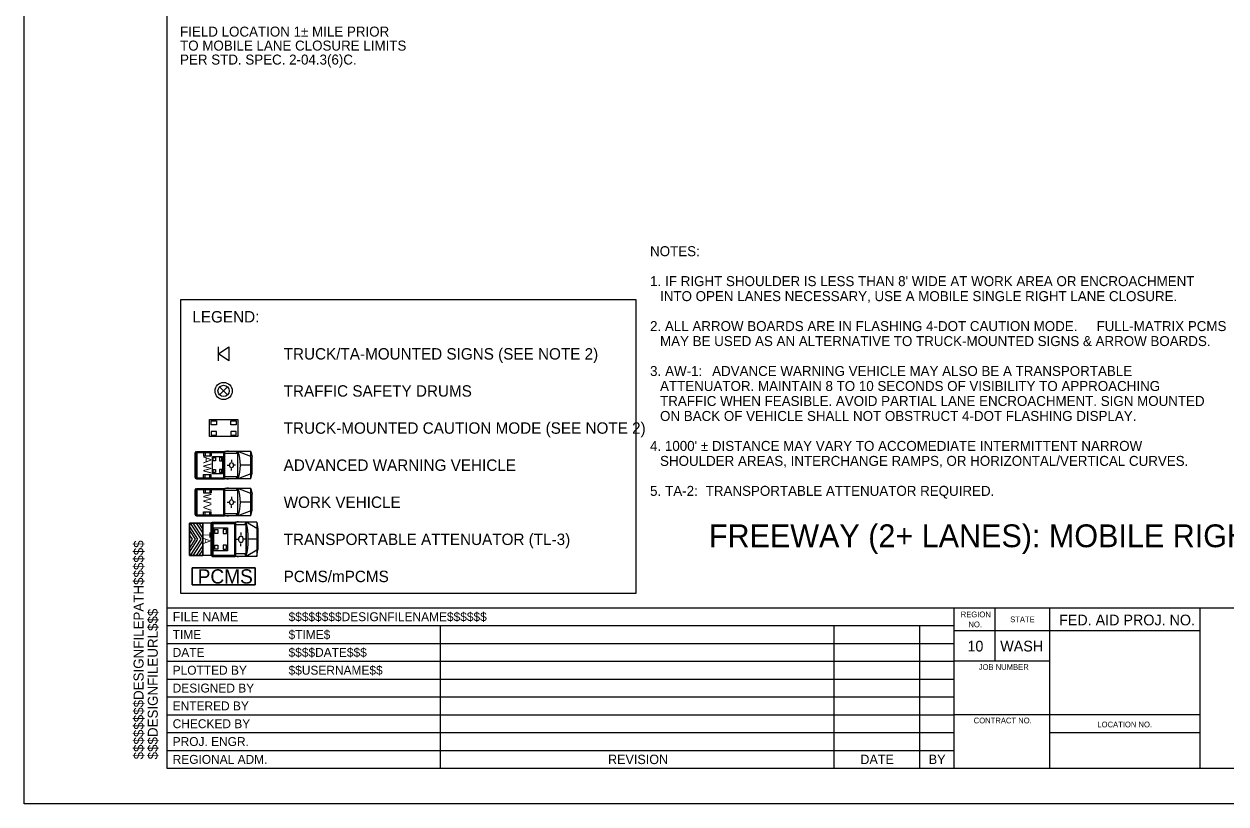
# Model space of a CAD drawing. Extents: x 0 to 17, y 0 to 11.
# Drawn here: x 0 to 8.43, y 0 to 5.47 of the extents above; entities that cross this region are included whole.
import ezdxf

# ---------------------------------------------------------------- set-up
doc = ezdxf.new("R2010")
doc.units = 0
for name, color, linetype in [('SH_GI_PlotLimits', 7, 'Continuous'), ('SH_GI_SheetBorder1', 7, 'Continuous'), ('SH_GI_SheetBorder2', 7, 'Continuous'), ('SH_GI_SheetBorder3', 7, 'Continuous'), ('SH_GI_SheetTextInCells', 7, 'Continuous'), ('SH_GI_TitleBlockText', 7, 'Continuous'), ('TR_WZ_PCMS', 7, 'Continuous'), ('TR_WZ_PortableChangeMessageSign', 7, 'Continuous'), ('TR_WZ_PortableSignMountBlk-Org', 7, 'Continuous'), ('TR_WZ_ProtectiveVehicle', 7, 'Continuous'), ('TR_WZ_TrafficSafetyDrum', 7, 'Continuous'), ('TR_WZ_TransportableAttenuator', 7, 'Continuous'), ('TR_WZ_WorkZoneTextCurrent', 7, 'Continuous')]:
    doc.layers.add(name, color=color, linetype=linetype)

msp = doc.modelspace()

# ---------------------------------------------------------------- linework, layer by layer
at = {"layer": 'SH_GI_PlotLimits'}
msp.add_lwpolyline([(0, 11), (17, 11), (17, 0), (0, 0)], close=True, dxfattribs=at)
at = {"layer": 'SH_GI_SheetBorder1'}
for p, q in [((8.245, 1.2125), (6.52, 1.2125)), ((1, 1.125), (2.92, 1.125)), ((2.92, 1.125), (6.52, 1.125)), ((1, 1), (2.92, 1)), ((2.92, 1), (6.52, 1)), ((1, 0.875), (2.92, 0.875)), ((2.92, 0.875), (6.52, 0.875)), ((1, 0.75), (2.92, 0.75)), ((2.92, 0.75), (6.52, 0.75)), ((1, 0.625), (2.92, 0.625)), ((2.92, 0.625), (6.52, 0.625)), ((1, 0.5), (2.92, 0.5)), ((2.92, 0.5), (6.52, 0.5)), ((7.1913, 0.5), (8.245, 0.5)), ((1, 0.375), (2.92, 0.375))]:
    msp.add_line(p, q, dxfattribs=at)
at = {"layer": 'SH_GI_SheetBorder2'}
for p, q in [((6.8073, 1), (6.8073, 1.375)), ((7.1913, 1), (6.52, 1)), ((8.245, 0.625), (6.52, 0.625)), ((2.92, 0.375), (6.52, 0.375))]:
    msp.add_line(p, q, dxfattribs=at)
at = {"layer": 'SH_GI_SheetBorder3'}
for p, q in [((1, 10.75), (1, 0.25)), ((1, 1.375), (16.75, 1.375)), ((6.52, 0.25), (6.52, 1.375)), ((7.1913, 0.25), (7.1913, 1.375)), ((8.245, 0.25), (8.245, 1.375)), ((1, 1.25), (6.52, 1.25)), ((2.92, 0.25), (2.92, 1.25)), ((5.68, 0.25), (5.68, 1.25)), ((6.28, 0.25), (6.28, 1.25)), ((1, 0.25), (16.75, 0.25))]:
    msp.add_line(p, q, dxfattribs=at)
at = {"layer": 'TR_WZ_PCMS'}
for points in [[(1.6191, 1.655), (1.6191, 1.535), (1.1791, 1.535), (1.1791, 1.655), (1.6191, 1.655)], [(1.1791, 1.655), (1.1791, 1.535), (1.6191, 1.535), (1.6191, 1.655), (1.1791, 1.655)]]:
    msp.add_lwpolyline(points, dxfattribs=at)
at = {"layer": 'TR_WZ_PortableSignMountBlk-Org'}
msp.add_line((1.3631, 3.105), (1.3631, 3.205), dxfattribs=at)
msp.add_lwpolyline([(1.3631, 3.155), (1.435, 3.205), (1.435, 3.105)], close=True, dxfattribs=at)
at = {"layer": 'TR_WZ_ProtectiveVehicle'}
for p, q in [((1.1993, 2.288), (1.1993, 2.462)), ((1.2035, 2.4678), (1.2078, 2.4678)), ((1.2078, 2.2822), (1.2078, 2.4678)), ((1.2085, 2.471), (1.406, 2.471)), ((1.2085, 2.279), (1.2085, 2.471)), ((1.2141, 2.2867), (1.2141, 2.4633)), ((1.2141, 2.4633), (1.4004, 2.4633)), ((1.2586, 2.4633), (1.2586, 2.4413)), ((1.2692, 2.4633), (1.2692, 2.4413)), ((1.3018, 2.4633), (1.3018, 2.4413)), ((1.3114, 2.4633), (1.3114, 2.4413)), ((1.4004, 2.2867), (1.4004, 2.4633)), ((1.406, 2.279), (1.406, 2.471)), ((1.4086, 2.279), (1.4086, 2.471)), ((1.59, 2.471), (1.4086, 2.471)), ((1.4976, 2.4561), (1.4086, 2.4561)), ((1.4334, 2.4737), (1.4225, 2.4737)), ((1.4881, 2.4561), (1.4976, 2.471)), ((1.4976, 2.279), (1.4976, 2.471)), ((1.4993, 2.279), (1.4993, 2.471)), ((1.59, 2.4358), (1.4993, 2.471)), ((1.59, 2.279), (1.59, 2.471)), ((1.59, 2.471), (1.5989, 2.4322)), ((1.1993, 2.3885), (1.2078, 2.3849)), ((1.1993, 2.3615), (1.2078, 2.3651)), ((1.2016, 2.375), (1.2055, 2.375)), ((1.2035, 2.3723), (1.2035, 2.3777)), ((1.2586, 2.4413), (1.3114, 2.4413)), ((1.4245, 2.3757), (1.4388, 2.3754)), ((1.4406, 2.3753), (1.4406, 2.3753)), ((1.4535, 2.4119), (1.4537, 2.3975)), ((1.4831, 2.3749), (1.471, 2.3749)), ((1.59, 2.375), (1.5171, 2.375)), ((1.5989, 2.3178), (1.5989, 2.4322)), ((1.2035, 2.2822), (1.2078, 2.2822)), ((1.2085, 2.279), (1.406, 2.279)), ((1.2141, 2.2867), (1.4004, 2.2867)), ((1.2586, 2.3087), (1.3114, 2.3087)), ((1.2586, 2.2867), (1.2586, 2.3087)), ((1.2692, 2.2867), (1.2692, 2.3087)), ((1.3018, 2.2867), (1.3018, 2.3087)), ((1.3114, 2.2867), (1.3114, 2.3087)), ((1.4976, 2.2939), (1.4086, 2.2939)), ((1.59, 2.279), (1.4086, 2.279)), ((1.4334, 2.2763), (1.4225, 2.2763)), ((1.4541, 2.3369), (1.4541, 2.3525)), ((1.4976, 2.279), (1.4861, 2.2939)), ((1.59, 2.3142), (1.4993, 2.279)), ((1.59, 2.279), (1.5989, 2.3178)), ((1.1993, 2.028), (1.1993, 2.202)), ((1.2035, 2.2078), (1.2078, 2.2078)), ((1.2078, 2.0222), (1.2078, 2.2078)), ((1.2085, 2.211), (1.406, 2.211)), ((1.2085, 2.019), (1.2085, 2.211)), ((1.2141, 2.0267), (1.2141, 2.2033)), ((1.2141, 2.2033), (1.4004, 2.2033)), ((1.2586, 2.2033), (1.2586, 2.1813)), ((1.2692, 2.2033), (1.2692, 2.1813)), ((1.3018, 2.2033), (1.3018, 2.1813)), ((1.3114, 2.2033), (1.3114, 2.1813)), ((1.4004, 2.0267), (1.4004, 2.2033)), ((1.406, 2.019), (1.406, 2.211)), ((1.4086, 2.019), (1.4086, 2.211)), ((1.59, 2.211), (1.4086, 2.211)), ((1.4976, 2.1961), (1.4086, 2.1961)), ((1.4334, 2.2137), (1.4225, 2.2137)), ((1.4881, 2.1961), (1.4976, 2.211)), ((1.4976, 2.019), (1.4976, 2.211)), ((1.4993, 2.019), (1.4993, 2.211)), ((1.59, 2.1758), (1.4993, 2.211)), ((1.59, 2.019), (1.59, 2.211)), ((1.59, 2.211), (1.5989, 2.1722)), ((1.1993, 2.1285), (1.2078, 2.1249)), ((1.2016, 2.115), (1.2055, 2.115)), ((1.2035, 2.1123), (1.2035, 2.1177)), ((1.2586, 2.1813), (1.3114, 2.1813)), ((1.4245, 2.1157), (1.4388, 2.1154)), ((1.4406, 2.1153), (1.4406, 2.1153)), ((1.4535, 2.1519), (1.4537, 2.1375)), ((1.4831, 2.1149), (1.471, 2.1149)), ((1.59, 2.115), (1.5171, 2.115)), ((1.5989, 2.0578), (1.5989, 2.1722)), ((1.1993, 2.1015), (1.2078, 2.1051)), ((1.2141, 2.0267), (1.4004, 2.0267)), ((1.2586, 2.0487), (1.3114, 2.0487)), ((1.2586, 2.0267), (1.2586, 2.0487)), ((1.2692, 2.0267), (1.2692, 2.0487)), ((1.3018, 2.0267), (1.3018, 2.0487)), ((1.3114, 2.0267), (1.3114, 2.0487)), ((1.4976, 2.0339), (1.4086, 2.0339)), ((1.4541, 2.0769), (1.4541, 2.0925)), ((1.4976, 2.019), (1.4861, 2.0339)), ((1.59, 2.0542), (1.4993, 2.019)), ((1.59, 2.019), (1.5989, 2.0578)), ((1.2035, 2.0222), (1.2078, 2.0222)), ((1.2085, 2.019), (1.406, 2.019)), ((1.59, 2.019), (1.4086, 2.019)), ((1.4334, 2.0163), (1.4225, 2.0163))]:
    msp.add_line(p, q, dxfattribs=at)
for centre, major_axis, start_param, end_param in [((1.2035, 2.462), (0, 0.00586), 0, 1.570796), ((1.3697, 2.375), (0, 0.2015), 4.215667, 5.208926), ((1.2035, 2.288), (0, -0.00586), 4.712389, 6.283185), ((1.2035, 2.202), (0, 0.00586), 0, 1.570796), ((1.3697, 2.115), (0, 0.2015), 4.215667, 5.208926), ((1.2035, 2.028), (0, -0.00586), 4.712389, 6.283185)]:
    msp.add_ellipse(centre, major_axis=major_axis, ratio=0.73155, start_param=start_param, end_param=end_param, dxfattribs=at)
for centre, major_axis in [((1.2035, 2.375), (0, -0.0027)), ((1.4541, 2.375), (0, -0.0185)), ((1.2035, 2.115), (0, -0.0027)), ((1.4541, 2.115), (0, -0.0185))]:
    msp.add_ellipse(centre, major_axis=major_axis, ratio=0.73155, dxfattribs=at)
at = {"layer": 'TR_WZ_TrafficSafetyDrum'}
for p, q in [((1.3708, 2.9233), (1.4273, 2.8667)), ((1.4273, 2.9233), (1.3708, 2.8667))]:
    msp.add_line(p, q, dxfattribs=at)
for radius in [0.06, 0.06, 0.04]:
    msp.add_circle((1.3991, 2.895), radius, dxfattribs=at)
at = {"layer": 'TR_WZ_TransportableAttenuator'}
for p, q in [((1.159, 1.9172), (1.159, 1.9464)), ((1.2191, 1.8559), (1.159, 1.9464)), ((1.159, 1.9464), (1.159, 1.9172)), ((1.1652, 1.9679), (1.1856, 1.9679)), ((1.1652, 1.9679), (1.2401, 1.8552)), ((1.1856, 1.9679), (1.1652, 1.9679)), ((1.2534, 1.8651), (1.1856, 1.9679)), ((1.2078, 1.9679), (1.2281, 1.9679)), ((1.2281, 1.9679), (1.2078, 1.9679)), ((1.2078, 1.9679), (1.2534, 1.8983)), ((1.2534, 1.9297), (1.2281, 1.9679)), ((1.2534, 1.7426), (1.2534, 1.9679)), ((1.3178, 1.9679), (1.2534, 1.9679)), ((1.3101, 1.9637), (1.3101, 1.7462)), ((1.3137, 1.971), (1.3172, 1.971)), ((1.3172, 1.971), (1.3172, 1.7389)), ((1.3178, 1.9749), (1.4803, 1.9749)), ((1.3178, 1.9749), (1.3178, 1.7349)), ((1.3178, 1.9675), (1.3178, 1.7426)), ((1.3224, 1.9654), (1.3224, 1.7445)), ((1.3224, 1.9654), (1.4757, 1.9654)), ((1.4757, 1.9654), (1.4757, 1.7445)), ((1.4803, 1.9749), (1.4803, 1.7349)), ((1.4825, 1.9749), (1.4825, 1.7349)), ((1.6317, 1.9749), (1.4825, 1.9749)), ((1.5557, 1.9563), (1.4825, 1.9563)), ((1.5028, 1.9783), (1.4938, 1.9783)), ((1.5557, 1.9749), (1.5462, 1.9563)), ((1.5557, 1.9749), (1.5557, 1.7349)), ((1.5571, 1.9749), (1.5571, 1.7349)), ((1.6317, 1.931), (1.5571, 1.9749)), ((1.6317, 1.9749), (1.6317, 1.7349)), ((1.6317, 1.9749), (1.639, 1.9265)), ((1.159, 1.9172), (1.1998, 1.8562)), ((1.159, 1.8239), (1.159, 1.8863)), ((1.1799, 1.8553), (1.159, 1.8863)), ((1.159, 1.8863), (1.159, 1.8239)), ((1.1998, 1.8562), (1.159, 1.7947)), ((1.159, 1.7653), (1.2191, 1.8559)), ((1.159, 1.8239), (1.1799, 1.8553)), ((1.2401, 1.8552), (1.1652, 1.7424)), ((1.2534, 1.9297), (1.2534, 1.8983)), ((1.2534, 1.8983), (1.2534, 1.9297)), ((1.2534, 1.8651), (1.2534, 1.845)), ((1.2534, 1.845), (1.2534, 1.8651)), ((1.3101, 1.8718), (1.3172, 1.8674)), ((1.312, 1.855), (1.3153, 1.855)), ((1.3137, 1.8583), (1.3137, 1.8516)), ((1.4881, 1.8551), (1.5014, 1.8551)), ((1.5051, 1.8545), (1.5051, 1.8545)), ((1.5199, 1.9025), (1.5199, 1.8831)), ((1.5517, 1.8551), (1.5384, 1.8551)), ((1.6317, 1.855), (1.5717, 1.855)), ((1.639, 1.9265), (1.639, 1.7834)), ((1.159, 1.7653), (1.159, 1.7947)), ((1.159, 1.7947), (1.159, 1.7653)), ((1.1852, 1.7424), (1.2534, 1.845)), ((1.2534, 1.8119), (1.2072, 1.7424)), ((1.2288, 1.7424), (1.2534, 1.7787)), ((1.2534, 1.8119), (1.2534, 1.7787)), ((1.2534, 1.7787), (1.2534, 1.8119)), ((1.3101, 1.838), (1.3172, 1.8426)), ((1.5199, 1.8074), (1.5199, 1.8268)), ((1.6317, 1.7789), (1.5571, 1.7349)), ((1.6317, 1.7349), (1.639, 1.7834)), ((1.1852, 1.7424), (1.1652, 1.7424)), ((1.1652, 1.7424), (1.1852, 1.7424)), ((1.2288, 1.7424), (1.2072, 1.7424)), ((1.2072, 1.7424), (1.2288, 1.7424)), ((1.3178, 1.7426), (1.2534, 1.7426)), ((1.3137, 1.7389), (1.3172, 1.7389)), ((1.3178, 1.7349), (1.4803, 1.7349)), ((1.3224, 1.7445), (1.4757, 1.7445)), ((1.5557, 1.7535), (1.4825, 1.7535)), ((1.6317, 1.7349), (1.4825, 1.7349)), ((1.5028, 1.7316), (1.4938, 1.7316)), ((1.5479, 1.7535), (1.5557, 1.7349))]:
    msp.add_line(p, q, dxfattribs=at)
for points in [[(1.4991, 2.695), (1.4991, 2.575), (1.2991, 2.575), (1.2991, 2.695)], [(1.3491, 2.685), (1.3491, 2.6583), (1.3116, 2.6583), (1.3116, 2.685)], [(1.4866, 2.685), (1.4866, 2.6583), (1.4491, 2.6583), (1.4491, 2.685)], [(1.3491, 2.585), (1.3491, 2.6117), (1.3116, 2.6117), (1.3116, 2.585)], [(1.4866, 2.585), (1.4866, 2.6117), (1.4491, 2.6117), (1.4491, 2.585)], [(1.3204, 2.435), (1.3924, 2.435), (1.3924, 2.315), (1.3204, 2.315)], [(1.3264, 2.4275), (1.3424, 2.4275), (1.3424, 2.405), (1.3264, 2.405)], [(1.3864, 2.4275), (1.3704, 2.4275), (1.3704, 2.405), (1.3864, 2.405)], [(1.3264, 2.345), (1.3424, 2.345), (1.3424, 2.3225), (1.3264, 2.3225)], [(1.3864, 2.345), (1.3704, 2.345), (1.3704, 2.3225), (1.3864, 2.3225)], [(1.2534, 1.7424), (1.159, 1.7424), (1.159, 1.9679), (1.2534, 1.9679)], [(1.3304, 1.935), (1.4264, 1.935), (1.4264, 1.775), (1.3304, 1.775)], [(1.3384, 1.925), (1.3597, 1.925), (1.3597, 1.895), (1.3384, 1.895)], [(1.4184, 1.925), (1.397, 1.925), (1.397, 1.895), (1.4184, 1.895)], [(1.3384, 1.815), (1.3597, 1.815), (1.3597, 1.785), (1.3384, 1.785)], [(1.4184, 1.815), (1.397, 1.815), (1.397, 1.785), (1.4184, 1.785)]]:
    msp.add_lwpolyline(points, close=True, dxfattribs=at)
msp.add_lwpolyline([(1.2534, 1.9679), (1.159, 1.9679), (1.159, 1.7424), (1.2534, 1.7426)], dxfattribs=at)
for centre, major_axis, start_param, end_param in [((1.3137, 1.9637), (0, 0.00732), 6.283185, 7.853982), ((1.4504, 1.8549), (0, 0.2519), 4.215852, 5.209111), ((1.3137, 1.7462), (0, -0.00732), 4.712389, 6.283185)]:
    msp.add_ellipse(centre, major_axis=major_axis, ratio=0.481608, start_param=start_param, end_param=end_param, dxfattribs=at)
for centre, major_axis, ratio in [((1.3137, 1.8549), (0, -0.00338), 0.481608), ((1.5199, 1.8549), (0, -0.0231), 0.642144), ((1.5199, 1.8549), (0, 0.0231), 0.642144)]:
    msp.add_ellipse(centre, major_axis=major_axis, ratio=ratio, dxfattribs=at)
at = {"layer": 'TR_WZ_WorkZoneTextCurrent'}
msp.add_lwpolyline([(1.1, 3.535), (4.2886, 3.535), (4.2886, 1.475), (1.1, 1.475)], close=True, dxfattribs=at)

# ---------------------------------------------------------------- texts
at = {"layer": 'SH_GI_SheetTextInCells'}
for s, height, p in [('REGION', 0.04, (6.5662, 1.3088)), ('FILE NAME', 0.065, (1.042, 1.28)), ('NO.', 0.04, (6.6206, 1.2387)), ('STATE', 0.04, (6.9129, 1.2738)), ('FED. AID PROJ. NO.', 0.075, (7.2558, 1.252)), ('TIME', 0.0625, (1.042, 1.1562)), ('10', 0.075, (6.6136, 1.0688)), ('WASH', 0.075, (6.8434, 1.0688)), ('DATE', 0.0625, (1.042, 1.0312)), ('PLOTTED BY', 0.0625, (1.042, 0.9062)), ('JOB NUMBER', 0.04, (6.6925, 0.94)), ('DESIGNED BY', 0.0625, (1.042, 0.7812)), ('ENTERED BY', 0.0625, (1.042, 0.6562)), ('CHECKED BY', 0.0625, (1.042, 0.5312)), ('CONTRACT NO.', 0.04, (6.6574, 0.565)), ('LOCATION NO.', 0.04, (7.5244, 0.537)), ('PROJ. ENGR.', 0.0625, (1.042, 0.4062)), ('REGIONAL ADM.', 0.0625, (1.042, 0.2812)), ('REVISION', 0.066, (4.0938, 0.2795)), ('DATE', 0.066, (5.8627, 0.2795)), ('BY', 0.066, (6.3424, 0.2795))]:
    msp.add_text(s, height=height, dxfattribs=at).set_placement(p)
at = {"layer": 'SH_GI_TitleBlockText'}
for s, p in [('$$$$$$$$DESIGNFILEPATH$$$$$$', (0.8377, 0.3125)), ('$$$DESIGNFILEURL$$$', (0.9375, 0.3125))]:
    msp.add_text(s, height=0.07, rotation=90, dxfattribs=at).set_placement(p)
for s, p in [('$$$$$$$$DESIGNFILENAME$$$$$$', (1.8545, 1.2812)), ('$TIME$', (1.8545, 1.1562)), ('$$$$DATE$$$', (1.8545, 1.0312)), ('$$USERNAME$$', (1.8545, 0.9062))]:
    msp.add_text(s, height=0.0625, dxfattribs=at).set_placement(p)
at = {"layer": 'TR_WZ_PCMS'}
msp.add_text('PCMS', height=0.1, rotation=360, dxfattribs=at).set_placement((1.2173, 1.545))
at = {"layer": 'TR_WZ_PortableChangeMessageSign'}
for s, p in [('FIELD LOCATION 1± MILE PRIOR ', (1.0938, 5.3789)), ('TO MOBILE LANE CLOSURE LIMITS ', (1.0938, 5.2809)), ('PER STD. SPEC. 2-04.3(6)C.', (1.0938, 5.1829))]:
    msp.add_text(s, height=0.07, rotation=360, dxfattribs=at).set_placement(p)
at = {"layer": 'TR_WZ_ProtectiveVehicle'}
for s, p in [('AW', (1.257, 2.4371)), ('WV', (1.257, 2.1743))]:
    msp.add_text(s, height=0.056, rotation=270, dxfattribs=at).set_placement(p)
at = {"layer": 'TR_WZ_TransportableAttenuator'}
msp.add_text('TA', height=0.048, rotation=270, dxfattribs=at).set_placement((1.2571, 1.9045))
at = {"layer": 'TR_WZ_WorkZoneTextCurrent'}
for s, height, p in [('NOTES:', 0.07, (4.3886, 3.8397)), ('1. ', 0.07, (4.3886, 3.6297)), ("IF RIGHT SHOULDER IS LESS THAN 8' WIDE AT WORK AREA OR ENCROACHMENT ", 0.07, (4.4943, 3.6297)), ('INTO OPEN LANES NECESSARY, USE A MOBILE SINGLE RIGHT LANE CLOSURE.', 0.07, (4.4586, 3.5247)), ('LEGEND:', 0.08, (1.18, 3.375)), ('2. ALL ARROW BOARDS ARE IN FLASHING 4-DOT CAUTION MODE. ', 0.07, (4.3886, 3.3147)), ('FULL-MATRIX PCMS ', 0.07, (7.5188, 3.3147)), ('MAY BE USED AS AN ALTERNATIVE TO TRUCK-MOUNTED SIGNS & ARROW BOARDS.', 0.07, (4.4586, 3.2097)), ('TRUCK/TA-MOUNTED SIGNS (SEE NOTE 2)', 0.08, (1.82, 3.115)), ('3. ', 0.07, (4.3886, 2.9997)), ('AW-1:', 0.07, (4.4943, 2.9997)), (' ADVANCE WARNING VEHICLE MAY ALSO BE A TRANSPORTABLE ', 0.07, (4.7978, 2.9997)), ('ATTENUATOR. MAINTAIN 8 TO 10 SECONDS OF VISIBILITY TO APPROACHING ', 0.07, (4.4586, 2.8947)), ('TRAFFIC SAFETY DRUMS', 0.08, (1.82, 2.855)), ('TRAFFIC WHEN FEASIBLE. AVOID PARTIAL LANE ENCROACHMENT. SIGN MOUNTED ', 0.07, (4.4586, 2.7897)), ('ON BACK OF VEHICLE SHALL NOT OBSTRUCT 4-DOT FLASHING DISPLAY.', 0.07, (4.4586, 2.6847)), ('TRUCK-MOUNTED CAUTION MODE (SEE NOTE 2)', 0.08, (1.82, 2.595)), ("4. 1000' ± DISTANCE MAY VARY TO ACCOMEDIATE INTERMITTENT NARROW ", 0.07, (4.3886, 2.4747)), ('ADVANCED WARNING VEHICLE', 0.08, (1.82, 2.335)), ('SHOULDER AREAS, INTERCHANGE RAMPS, OR HORIZONTAL/VERTICAL CURVES. ', 0.07, (4.4586, 2.3697)), ('5. ', 0.07, (4.3886, 2.1597)), ('TA-2:', 0.07, (4.4943, 2.1597)), (' TRANSPORTABLE ATTENUATOR REQUIRED.', 0.07, (4.7527, 2.1597)), ('WORK VEHICLE', 0.08, (1.82, 2.075)), ('FREEWAY (2+ LANES): MOBILE RIGHT SHOULDER CLOSURE, EXCLUDING PAVEMENT MARKING OPERATIONS', 0.16, (4.8007, 1.7997)), ('TRANSPORTABLE ATTENUATOR (TL-3)', 0.08, (1.82, 1.815)), ('PCMS/mPCMS', 0.08, (1.82, 1.555))]:
    msp.add_text(s, height=height, rotation=360, dxfattribs=at).set_placement(p)

doc.saveas('drawing.dxf')
